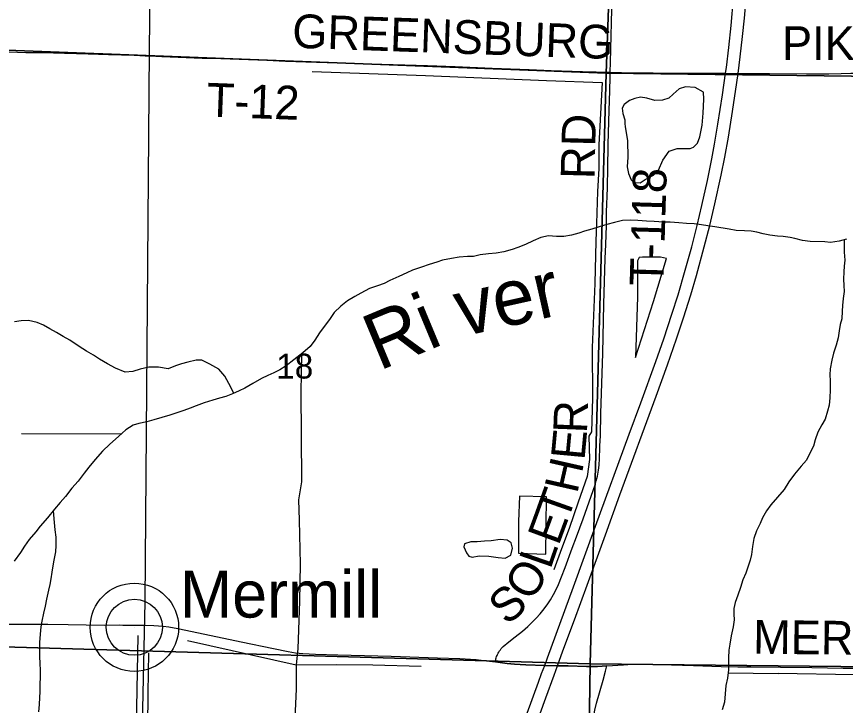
# Model space of a CAD drawing. Extents: x 0 to 39.4, y 0 to 22.
# Drawn here: x 5.438 to 6.833, y 18.256 to 19.416 of the extents above; entities that cross this region are included whole.
import ezdxf

# ---------------------------------------------------------------- set-up
doc = ezdxf.new("R2010")
doc.units = 0
for name, color, linetype in [('GM_X_County_Road', 7, 'Continuous'), ('GM_X_County_Road_Text', 7, 'Continuous'), ('GM_X_Interstate_Route', 7, 'Continuous'), ('GM_X_Major_River', 7, 'Continuous'), ('GM_X_Minor_Lake', 7, 'Continuous'), ('GM_X_Minor_River', 7, 'Continuous'), ('GM_X_Minor_River_Text', 7, 'Continuous'), ('GM_X_Rail_Line', 7, 'Continuous'), ('GM_X_Section', 7, 'Continuous'), ('GM_X_Section_Text', 7, 'Continuous'), ('GM_X_Township_Road', 7, 'Continuous'), ('GM_X_Township_Road_Text', 7, 'Continuous'), ('GM_X_Unincorporated', 7, 'Continuous'), ('GM_X_Unincorporated_Location', 7, 'Continuous'), ('GM_X_Unincorporated_Text', 7, 'Continuous')]:
    doc.layers.add(name, color=color, linetype=linetype)

msp = doc.modelspace()

# ---------------------------------------------------------------- linework, layer by layer
at = {"layer": 'GM_X_County_Road'}
for points in [[(5.4252, 18.3927), (5.4594, 18.3926), (5.4904, 18.3925), (5.5243, 18.392), (5.5548, 18.3914), (5.5855, 18.3913), (5.6103, 18.3914), (5.6165, 18.3912), (5.6379, 18.3909), (5.641, 18.391), (5.6533, 18.3908), (5.6688, 18.3903), (5.6844, 18.3892), (5.6937, 18.3881), (5.7091, 18.3854), (5.776, 18.3715), (5.8156, 18.3631), (5.8703, 18.3516), (5.8947, 18.3466), (5.9069, 18.3446), (5.9192, 18.3433), (5.9409, 18.3421), (5.9782, 18.3412), (6.0683, 18.3387), (6.146, 18.3362), (6.1836, 18.3347)], [(6.1836, 18.3347), (6.1926, 18.3343), (6.2112, 18.3331), (6.2236, 18.3318), (6.2437, 18.3291)], [(6.2437, 18.3291), (6.2636, 18.3264), (6.2759, 18.3252), (6.2945, 18.3242), (6.3265, 18.3233), (6.348, 18.3228), (6.366, 18.3224), (6.397, 18.3216), (6.4156, 18.3217), (6.431, 18.3224)], [(6.431, 18.3224), (6.459, 18.3245), (6.4745, 18.3252), (6.4932, 18.3253), (6.5182, 18.3248)], [(6.5182, 18.3248), (6.5212, 18.3248), (6.5771, 18.3229), (6.6237, 18.3216), (6.6517, 18.3211), (6.6735, 18.3207), (6.7232, 18.3201), (6.776, 18.3197), (6.8289, 18.3189), (6.8693, 18.3188), (6.9563, 18.3179), (7.0061, 18.3174), (7.034, 18.3171), (7.0962, 18.3169), (7.1304, 18.3168), (7.2112, 18.316), (7.2672, 18.3155), (7.3884, 18.3148), (7.407, 18.3146)]]:
    msp.add_lwpolyline(points, dxfattribs=at)
at = {"layer": 'GM_X_Interstate_Route'}
for points in [[(6.2862, 18.2135), (6.316, 18.2953), (6.3214, 18.3099), (6.3265, 18.3233), (6.3314, 18.336), (6.375, 18.4558), (6.4123, 18.558), (6.4687, 18.7128), (6.4881, 18.7653), (6.5136, 18.8354), (6.527, 18.8735), (6.5407, 18.9149), (6.5509, 18.9475), (6.5632, 18.9893), (6.5739, 19.0283), (6.5831, 19.0644), (6.5911, 19.0977), (6.6004, 19.1402), (6.608, 19.1768), (6.6124, 19.2012), (6.6181, 19.235), (6.6257, 19.2841), (6.631, 19.3206), (6.6324, 19.3303), (6.6366, 19.3643), (6.6405, 19.4014), (6.6445, 19.4478)], [(6.3091, 18.2161), (6.3284, 18.2689), (6.3423, 18.3068), (6.348, 18.3228), (6.357, 18.3478), (6.3765, 18.4002), (6.3979, 18.4586), (6.4286, 18.5433), (6.4532, 18.6105), (6.514, 18.7769), (6.5332, 18.8295), (6.5486, 18.8734), (6.5603, 18.9088), (6.5723, 18.9474), (6.5819, 18.9802), (6.5951, 19.0281), (6.6043, 19.0643), (6.6128, 19.1006), (6.6235, 19.1491), (6.6296, 19.1796), (6.6357, 19.2132), (6.6427, 19.2561), (6.65, 19.3053), (6.652, 19.3204), (6.6557, 19.3485), (6.6597, 19.3824), (6.6627, 19.4133), (6.666, 19.4536)]]:
    msp.add_lwpolyline(points, dxfattribs=at)
at = {"layer": 'GM_X_Major_River'}
for points in [[(6.7281, 19.0456), (6.7182, 19.0464), (6.7057, 19.0479), (6.6943, 19.0502), (6.6833, 19.0529), (6.6738, 19.0545), (6.6628, 19.0553), (6.6488, 19.0561), (6.6371, 19.058), (6.6128, 19.0619), (6.601, 19.0638), (6.5904, 19.0654), (6.5779, 19.0673), (6.5654, 19.0677), (6.5521, 19.0685), (6.5377, 19.0701), (6.5263, 19.0701), (6.5107, 19.0709), (6.4979, 19.0717), (6.4834, 19.0729), (6.4717, 19.0733), (6.4576, 19.0726), (6.444, 19.0692), (6.4311, 19.0662), (6.4181, 19.0621), (6.4056, 19.0583), (6.3935, 19.0545), (6.384, 19.0512), (6.3718, 19.0478), (6.3589, 19.0459), (6.3464, 19.0456), (6.3327, 19.0471), (6.3198, 19.0441), (6.3073, 19.0385), (6.294, 19.032), (6.2814, 19.0271), (6.2719, 19.0241), (6.2579, 19.02), (6.245, 19.0174), (6.2321, 19.0163), (6.2177, 19.0148), (6.2067, 19.0122), (6.1968, 19.0118), (6.1824, 19.0107), (6.1698, 19.0089), (6.1546, 19.0059), (6.1452, 19.0025), (6.1319, 18.9983), (6.1189, 18.9942), (6.1038, 18.9889), (6.0943, 18.9844), (6.081, 18.9784), (6.0661, 18.9716), (6.0566, 18.9667), (6.0452, 18.9629), (6.0319, 18.958), (6.0171, 18.9504), (6.0072, 18.9448), (5.9947, 18.9372), (5.9833, 18.9285), (5.9722, 18.9179), (5.9642, 18.9062), (5.9551, 18.894), (5.9475, 18.8834), (5.9399, 18.8709), (5.9319, 18.8607), (5.9193, 18.8497), (5.9045, 18.838), (5.8915, 18.8281), (5.8809, 18.8213), (5.8706, 18.816), (5.8607, 18.8115), (5.8501, 18.8066), (5.8353, 18.7983), (5.8216, 18.7903), (5.8121, 18.7858), (5.8011, 18.7805), (5.7897, 18.7764), (5.779, 18.7734), (5.7677, 18.77), (5.7536, 18.7658), (5.7399, 18.7606), (5.7301, 18.7568), (5.719, 18.7527), (5.7057, 18.7481), (5.6955, 18.7447), (5.6822, 18.741), (5.6689, 18.7368), (5.6568, 18.7338), (5.6435, 18.7308), (5.634, 18.7278), (5.6214, 18.7199), (5.6092, 18.7089), (5.5944, 18.6957), (5.5822, 18.6839), (5.57, 18.6703), (5.559, 18.657), (5.5514, 18.6472), (5.5411, 18.6335), (5.5308, 18.6218), (5.5202, 18.6078)], [(6.7476, 19.0425), (6.7395, 19.044), (6.7281, 19.0456)], [(6.8343, 19.0413), (6.822, 19.0377), (6.8075, 19.0354), (6.7981, 19.0367), (6.7734, 19.0371), (6.7605, 19.0389), (6.7476, 19.0425)], [(5.5202, 18.6078), (5.511, 18.5979), (5.5015, 18.5862), (5.4897, 18.5721), (5.4775, 18.5581), (5.4699, 18.5483), (5.4588, 18.5354), (5.4512, 18.524), (5.444, 18.5134), (5.4337, 18.499)]]:
    msp.add_lwpolyline(points, dxfattribs=at)
at = {"layer": 'GM_X_Minor_Lake'}
for p, q in [((6.4616, 19.2363), (6.4619, 19.2302)), ((6.5216, 19.0109), (6.4912, 19.011)), ((6.2843, 18.6082), (6.2823, 18.5657)), ((6.2362, 18.5331), (6.2252, 18.5328))]:
    msp.add_line(p, q, dxfattribs=at)
for points in [[(6.4619, 19.2302), (6.4638, 19.2211), (6.4657, 19.2066), (6.4663, 19.1793), (6.4655, 19.1633), (6.4674, 19.1516), (6.4723, 19.1413), (6.4764, 19.1367), (6.4874, 19.1359), (6.4954, 19.1416), (6.5095, 19.1488), (6.5179, 19.1575), (6.5251, 19.1742), (6.5362, 19.1897), (6.5495, 19.1942), (6.5711, 19.1942), (6.5768, 19.196), (6.5836, 19.2032), (6.5879, 19.2135), (6.5917, 19.2332), (6.5933, 19.2537), (6.5945, 19.2769), (6.5938, 19.2887), (6.5798, 19.2967), (6.5635, 19.2979), (6.5528, 19.2945), (6.5429, 19.2854), (6.5353, 19.279), (6.5247, 19.2752), (6.5118, 19.2749), (6.4985, 19.2787), (6.4879, 19.2806), (6.4784, 19.278), (6.4693, 19.2746), (6.4602, 19.2682), (6.4571, 19.2617), (6.4582, 19.253), (6.4616, 19.242), (6.4616, 19.2363)], [(6.4912, 19.011), (6.4855, 19.0102), (6.4828, 19.0049), (6.4826, 18.9441), (6.4793, 18.842), (6.5099, 18.9361), (6.5314, 19.0089), (6.5216, 19.0109)], [(6.2823, 18.5657), (6.2825, 18.5121), (6.3287, 18.5104), (6.3294, 18.6073), (6.2843, 18.6082)], [(6.2252, 18.5328), (6.2127, 18.5317), (6.2021, 18.5317), (6.1918, 18.5283), (6.1907, 18.523), (6.1948, 18.5127), (6.199, 18.5074), (6.2047, 18.5055), (6.2164, 18.5081), (6.2324, 18.5073), (6.2483, 18.505), (6.2601, 18.5042), (6.2696, 18.5091), (6.2722, 18.5209), (6.27, 18.53), (6.2636, 18.5342), (6.2518, 18.5354), (6.2362, 18.5331)]]:
    msp.add_lwpolyline(points, dxfattribs=at)
at = {"layer": 'GM_X_Minor_River'}
for points in [[(5.9352, 19.3236), (6.1261, 19.317), (6.3294, 19.3084), (6.4235, 19.3051), (6.4175, 19.2003), (6.4177, 19.1604), (6.4153, 19.1217), (6.4136, 19.0678), (6.4128, 19.0378), (6.411, 18.9664), (6.4065, 18.8585), (6.407, 18.7734), (6.4053, 18.7169), (6.4007, 18.7097), (6.4017, 18.6701), (6.3982, 18.6413), (6.3829, 18.5984), (6.3676, 18.554), (6.355, 18.5195), (6.3419, 18.4842)], [(6.8306, 19.0403), (6.8308, 19.0193), (6.8317, 19.0056), (6.8308, 18.9957), (6.8298, 18.9862), (6.8296, 18.9737), (6.8302, 18.9631), (6.8304, 18.9532), (6.829, 18.9411), (6.828, 18.9293), (6.8274, 18.9198), (6.8265, 18.9073), (6.824, 18.8975), (6.8219, 18.8869), (6.8202, 18.8752), (6.8169, 18.8627), (6.8128, 18.8491), (6.8096, 18.8377), (6.807, 18.823), (6.8064, 18.8127), (6.807, 18.8025), (6.8071, 18.7877), (6.8065, 18.774), (6.8055, 18.7615), (6.8026, 18.7517), (6.7986, 18.7381), (6.7927, 18.7283), (6.7864, 18.7163), (6.7816, 18.7031), (6.7787, 18.6925), (6.7728, 18.6808), (6.7669, 18.6691), (6.758, 18.6591), (6.7471, 18.6456), (6.7373, 18.6325), (6.7295, 18.6197)], [(5.8034, 18.7816), (5.7951, 18.7984), (5.7883, 18.8106), (5.7781, 18.8224), (5.7629, 18.8308), (5.7497, 18.8377), (5.7402, 18.8373), (5.7257, 18.8343), (5.7151, 18.8313), (5.7052, 18.8279), (5.6927, 18.823), (5.6764, 18.8257), (5.6605, 18.8254), (5.6457, 18.822), (5.6335, 18.8182), (5.6206, 18.8175), (5.6043, 18.824), (5.5907, 18.8313), (5.5774, 18.8389), (5.5672, 18.8458), (5.5551, 18.8527), (5.543, 18.8607), (5.5271, 18.871), (5.5161, 18.8775), (5.5051, 18.8843), (5.4937, 18.8904), (5.4827, 18.8962), (5.4721, 18.9007), (5.4577, 18.9042), (5.4452, 18.9035), (5.4342, 18.902)], [(5.9174, 18.8482), (5.916, 18.7832), (5.9166, 18.7114), (5.9171, 18.6324), (5.9124, 18.6024), (5.9131, 18.5679), (5.9148, 18.4938), (5.9138, 18.4315), (5.9113, 18.351), (5.9085, 18.3244), (5.908, 18.2837), (5.9039, 18.1831), (5.8974, 18.0437), (5.8945, 17.9362), (5.8954, 17.8663)], [(5.6134, 18.7127), (5.4457, 18.7132)], [(6.7295, 18.6197), (6.7069, 18.5937), (6.7, 18.5838), (6.6932, 18.5721), (6.689, 18.5626), (6.6832, 18.5497), (6.6786, 18.5368), (6.6763, 18.5235), (6.6748, 18.5102), (6.6721, 18.5007), (6.6686, 18.4886), (6.6648, 18.4787), (6.6602, 18.4673), (6.656, 18.4544), (6.6514, 18.4415), (6.6472, 18.429), (6.6449, 18.4191), (6.6449, 18.4096), (6.6456, 18.4001), (6.644, 18.3883), (6.6406, 18.3732), (6.6383, 18.3591), (6.6367, 18.3489), (6.6359, 18.336), (6.6358, 18.3158), (6.6343, 18.3018), (6.6316, 18.2892), (6.63, 18.2756), (6.6289, 18.2615), (6.6254, 18.2486)], [(5.4993, 18.5836), (5.501, 18.5638), (5.5021, 18.5516), (5.5036, 18.5394), (5.504, 18.5254), (5.5032, 18.5147), (5.5005, 18.5007), (5.4989, 18.4912), (5.497, 18.4802), (5.4954, 18.4692), (5.4939, 18.4597), (5.4916, 18.4498), (5.4881, 18.4346), (5.4858, 18.4232), (5.4827, 18.4111), (5.48, 18.3978), (5.4785, 18.3883), (5.4773, 18.3758), (5.4761, 18.3621), (5.4761, 18.3492), (5.4764, 18.3393), (5.4768, 18.3256), (5.4771, 18.3162), (5.477, 18.2789), (5.4762, 18.2694), (5.4758, 18.2573), (5.4746, 18.2451)], [(5.6416, 18.3738), (5.6397, 18.2519), (5.6368, 17.9388), (5.6359, 17.7474), (5.6326, 17.5373), (5.6301, 17.3295), (5.6288, 17.1521), (5.6277, 17.0461), (5.6263, 16.8296), (5.6266, 16.6901), (5.626, 16.6134), (5.6259, 16.4588), (5.6242, 16.3714), (5.6213, 16.1704), (5.6181, 16.0048), (5.6172, 15.8411), (5.614, 15.6538), (5.6138, 15.5695), (5.6113, 15.4942), (5.6102, 15.3905), (5.6089, 15.3442), (5.6082, 15.2177), (5.6092, 15.1099)], [(5.7254, 18.3652), (5.9085, 18.3244), (5.9768, 18.3246), (6.0375, 18.3244), (6.1187, 18.3223)], [(5.6597, 18.3445), (5.6584, 18.2769), (5.6576, 18.161), (5.6566, 18.0657), (5.6555, 17.965), (5.6525, 17.8579), (5.653, 17.7762), (5.6505, 17.701), (5.6494, 17.592), (5.6494, 17.4613), (5.6469, 17.3864), (5.6467, 17.3078), (5.646, 17.2026), (5.645, 17.1091), (5.6439, 17.0001), (5.6428, 16.899), (5.6424, 16.7589), (5.6428, 16.6559)], [(6.6353, 18.3107), (6.7195, 18.3096)], [(8.2895, 18.2925), (8.009, 18.2944), (7.7819, 18.2978), (7.5668, 18.296), (7.3865, 18.2997), (7.3591, 18.3006), (7.2691, 18.3018), (7.1389, 18.3046), (7.0268, 18.3051), (6.8479, 18.3072), (6.7195, 18.3096)]]:
    msp.add_lwpolyline(points, dxfattribs=at)
at = {"layer": 'GM_X_Rail_Line'}
msp.add_lwpolyline([(5.6115, 14.1), (5.6226, 15.3413), (5.6228, 15.3801), (5.635, 16.7601), (5.6441, 17.4388), (5.6457, 18.044), (5.6539, 18.4301), (5.6611, 19.3588), (5.6728, 20.3992), (5.6755, 20.8483), (5.6758, 20.9)], dxfattribs=at)
at = {"layer": 'GM_X_Section'}
for points in [[(5.4196, 20.3595), (6.4661, 20.3227), (6.4302, 19.3208), (5.4065, 19.3604), (5.4059, 19.4006)], [(6.4661, 20.3227), (7.4647, 20.3092), (7.439, 19.3083), (6.4302, 19.3208)], [(5.4065, 19.3604), (6.4302, 19.3208), (6.4032, 18.3261), (5.3956, 18.3552), (5.3953, 18.3924)], [(6.4302, 19.3208), (7.439, 19.3083), (7.4046, 18.3152), (6.4032, 18.3261)], [(5.3956, 18.3552), (6.4032, 18.3261), (6.3887, 17.3403), (5.3882, 17.3864)], [(7.4046, 18.3152), (7.3784, 17.3348), (6.3887, 17.3403), (6.4032, 18.3261)]]:
    msp.add_lwpolyline(points, close=True, dxfattribs=at)
at = {"layer": 'GM_X_Township_Road'}
for points in [[(6.4367, 19.3224), (6.4371, 19.3393), (6.4401, 19.451), (6.4428, 19.553), (6.4445, 19.6076), (6.4458, 19.65), (6.4469, 19.6842), (6.4478, 19.7184), (6.4487, 19.7607), (6.4492, 19.7806), (6.4497, 19.7911), (6.4505, 19.8203)], [(5.4118, 19.3567), (5.4254, 19.3565), (5.4532, 19.3559), (5.4811, 19.3556), (5.5182, 19.3547), (5.5584, 19.3535), (5.5923, 19.3525), (5.6355, 19.3511), (5.654, 19.35), (5.672, 19.3493)], [(5.672, 19.3493), (5.6727, 19.3493), (5.682, 19.3489), (5.7099, 19.3476), (5.7503, 19.3462), (5.7814, 19.3455), (5.828, 19.3436), (5.8591, 19.3426), (5.8901, 19.3413), (5.9243, 19.3401), (6.0144, 19.3372), (6.1294, 19.3336), (6.176, 19.3318), (6.2381, 19.3294), (6.3002, 19.3268), (6.3375, 19.3256), (6.3903, 19.3239), (6.4367, 19.3224)], [(6.4196, 18.6929), (6.4202, 18.7098), (6.4211, 18.7477), (6.4241, 18.849), (6.4263, 18.9317), (6.4285, 19.0088), (6.4294, 19.0324), (6.4303, 19.0641), (6.4307, 19.084), (6.4312, 19.1033), (6.4314, 19.1101), (6.432, 19.1312), (6.4326, 19.1592), (6.4336, 19.2015), (6.4352, 19.258), (6.436, 19.291), (6.4366, 19.314), (6.4367, 19.3224)], [(6.4367, 19.3224), (6.4751, 19.3213), (6.4829, 19.3213)], [(6.4829, 19.3213), (6.5093, 19.3212), (6.587, 19.3209), (6.6211, 19.3206), (6.631, 19.3206), (6.652, 19.3204), (6.7051, 19.3202), (6.7672, 19.3198), (6.7888, 19.3199)], [(6.7888, 19.3199), (6.8045, 19.3199), (6.8256, 19.3203)], [(6.8256, 19.3203), (6.8417, 19.3206), (6.8604, 19.3207), (6.8852, 19.3205), (6.907, 19.3203), (6.9367, 19.3202)], [(6.2437, 18.3291), (6.2442, 18.3323), (6.2445, 18.3342), (6.245, 18.3363), (6.2455, 18.3381), (6.2463, 18.3401), (6.247, 18.3417), (6.2481, 18.344), (6.2492, 18.3458), (6.2504, 18.3476), (6.2519, 18.3496), (6.2534, 18.3515), (6.2549, 18.3533), (6.2566, 18.355), (6.266, 18.3629), (6.277, 18.3716), (6.2892, 18.3812), (6.2982, 18.3889), (6.3045, 18.3949), (6.3123, 18.4029), (6.3189, 18.4104), (6.3255, 18.4186), (6.3317, 18.4271), (6.3362, 18.4339), (6.3412, 18.4425), (6.3465, 18.4524), (6.3499, 18.4597), (6.355, 18.4724), (6.361, 18.4881), (6.3728, 18.5208), (6.3799, 18.5401), (6.3911, 18.5704), (6.4083, 18.6178), (6.4114, 18.6272), (6.4134, 18.6344), (6.4152, 18.6423), (6.417, 18.6521), (6.418, 18.6607), (6.4188, 18.6719), (6.4195, 18.6899), (6.4196, 18.6929)], [(6.431, 18.3224), (6.4156, 18.3217), (6.397, 18.3216), (6.366, 18.3224), (6.348, 18.3228), (6.3265, 18.3233), (6.2945, 18.3242), (6.2759, 18.3252), (6.2636, 18.3264), (6.2437, 18.3291)], [(6.4068, 18.197), (6.4073, 18.22), (6.4079, 18.2293), (6.409, 18.2385), (6.4107, 18.2477), (6.4137, 18.2598), (6.4247, 18.2986), (6.4287, 18.3137), (6.431, 18.3224)]]:
    msp.add_lwpolyline(points, dxfattribs=at)
at = {"layer": 'GM_X_Unincorporated'}
for radius in [0.0744, 0.0472]:
    msp.add_circle((5.6359, 18.3875), radius, dxfattribs=at)
at = {"layer": 'GM_X_Unincorporated_Location'}
msp.add_line((5.6359, 18.3875), (5.6359, 18.3875), dxfattribs=at)

# ---------------------------------------------------------------- texts
at = {"layer": 'GM_X_County_Road_Text'}
msp.add_text('MERMILL', height=0.05682, rotation=359.4049, dxfattribs=at).set_placement((6.6771, 18.343))
at = {"layer": 'GM_X_Minor_River_Text'}
for s, rotation, p in [('ver', 12.5793, (6.1865, 18.8766)), ('Ri', 22.5779, (6.0477, 18.819))]:
    msp.add_text(s, height=0.09475, rotation=rotation, dxfattribs=at).set_placement(p)
at = {"layer": 'GM_X_Section_Text'}
msp.add_text('18', height=0.04186, rotation=0, dxfattribs=at).set_placement((5.8747, 18.8065))
at = {"layer": 'GM_X_Township_Road_Text'}
for s, height, rotation, p in [('GREENSBURG', 0.05682, 357.9544, (5.9009, 19.3638)), ('PIKE', 0.05682, 0, (6.7259, 19.343)), ('T-12', 0.05682, 357.8816, (5.7568, 19.2479)), ('RD', 0.05682, 88.5399, (6.4102, 19.1419)), ('T-118', 0.05682, 88.3161, (6.5262, 18.962)), ('R', 0.0568, 87.8349, (6.3976, 18.7137)), ('E', 0.0568, 84.6583, (6.3934, 18.6679)), ('H', 0.0568, 77.228, (6.3811, 18.6112)), ('T', 0.0568, 70.3788, (6.3647, 18.5641)), ('E', 0.0568, 69.784, (6.3498, 18.5236)), ('L', 0.0568, 70.8526, (6.336, 18.4837)), ('O', 0.0568, 58.8887, (6.3046, 18.4292)), ('S', 0.0568, 40.9682, (6.2633, 18.3893))]:
    msp.add_text(s, height=height, rotation=rotation, dxfattribs=at).set_placement(p)
at = {"layer": 'GM_X_Unincorporated_Text'}
msp.add_text('Mermill', height=0.07898, rotation=0, dxfattribs=at).set_placement((5.7126, 18.4039))

doc.saveas('drawing.dxf')
